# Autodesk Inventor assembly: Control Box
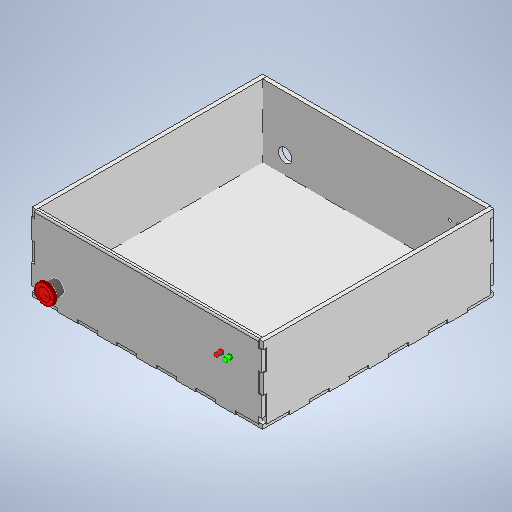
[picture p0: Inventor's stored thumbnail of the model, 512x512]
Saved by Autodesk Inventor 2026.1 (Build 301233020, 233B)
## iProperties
Created: 2026-11
Part Number: Control Box
Document SubType Name: Assembly
Designer: hp
Author: hp
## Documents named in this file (8)
- C:\Users\hp\Documents\Inventor\DOM1_CartesianRobot\Control Box.iam
- C:\Users\hp\Documents\Inventor\DOM1_CartesianRobot\Bottom of Control Box.ipt
- C:\Users\hp\Documents\Inventor\DOM1_CartesianRobot\Right of Control Box.ipt
- C:\Users\hp\Documents\Inventor\DOM1_CartesianRobot\Left of Control Box.ipt
- C:\Users\hp\Documents\Inventor\DOM1_CartesianRobot\Front of Control Box.ipt
- C:\Users\hp\Documents\Inventor\DOM1_CartesianRobot\Back of Control Box.ipt
- C:\Users\hp\Documents\Inventor\DOM1_CartesianRobot\STEP_LED_DIODE_5mm.ipt
- C:\Users\hp\Documents\Inventor\DOM1_CartesianRobot\Emergency stop switch_AB6-A.ipt
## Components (8 placed, 7 different names)
1. Bottom of Control Box:1 — Mate:1, Flush:1, Mate:2, Mate:3, Flush:2, Mate:4, Mate:5, Flush:3, Mate:6, Flush:5
2. Right of Control Box:1
3. Left of Control Box:1 — Mate:1, Flush:1, Mate:2, Flush:4
4. Front of Control Box:1 — Mate:5, Flush:3, Flush:4
5. Back of Control Box:1 — Mate:6, Flush:5, Mate:7
6. STEP_LED_DIODE_5mm:1 — Mate:8, Mate:10
7. STEP_LED_DIODE_5mm:2 — Mate:9, Mate:11
8. Emergency stop switch_AB6-A:1 — Mate:12, Mate:13
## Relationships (18: Mate 13, Flush 5)
- Mate:1: Bottom of Control Box:1 ↔ Left of Control Box:1
- Flush:1: Bottom of Control Box:1 ↔ Left of Control Box:1
- Mate:2: Bottom of Control Box:1 ↔ Left of Control Box:1
- Mate:3: Bottom of Control Box:1
- Flush:2: Bottom of Control Box:1
- Mate:4: Bottom of Control Box:1
- Mate:5: Bottom of Control Box:1 ↔ Front of Control Box:1
- Flush:3: Bottom of Control Box:1 ↔ Front of Control Box:1
- Flush:4: Left of Control Box:1 ↔ Front of Control Box:1
- Mate:6: Bottom of Control Box:1 ↔ Back of Control Box:1
- Flush:5: Bottom of Control Box:1 ↔ Back of Control Box:1
- Mate:7: Back of Control Box:1
- Mate:8: STEP_LED_DIODE_5mm:1
- Mate:9: STEP_LED_DIODE_5mm:2
- Mate:10: STEP_LED_DIODE_5mm:1
- Mate:11: STEP_LED_DIODE_5mm:2
- Mate:12: Emergency stop switch_AB6-A:1
- Mate:13: Emergency stop switch_AB6-A:1
